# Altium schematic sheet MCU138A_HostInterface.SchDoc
size 431 x 279 mm; Date: Not shown in title block; ApprovedBy: Not shown in title block; CheckedBy: Not shown in title block; Author: Not shown in title block; CompanyName: Not shown in title block; DrawnBy: Jonathan Cohen; Engineer: Not shown in title block; Organization: Not shown in title block; Address1: Not shown in title block; Address2: Not shown in title block; Address3: Not shown in title block; Address4: Not shown in title block; DocumentNumber: 2; Revision: Use project parameter SCH_Rev; SheetNumber: 2; SheetTotal: 3; PageSetup: Record=PageOptions¦CenterHorizontal=True¦CenterVertical=True¦PrintScale=1.00¦XCorrection=1.00¦YCorrection=1.00¦PrintKind=0¦BorderSize=5000000¦LeftOffset=0¦BottomOffset=0¦Orientation=2¦PaperLength=1000¦PaperWidth=1000¦Scale=100¦PaperSource=15¦PrintQuality=600¦MediaType=1¦DitherType=10¦PaperKind=Letter¦PrintScaleMode=1
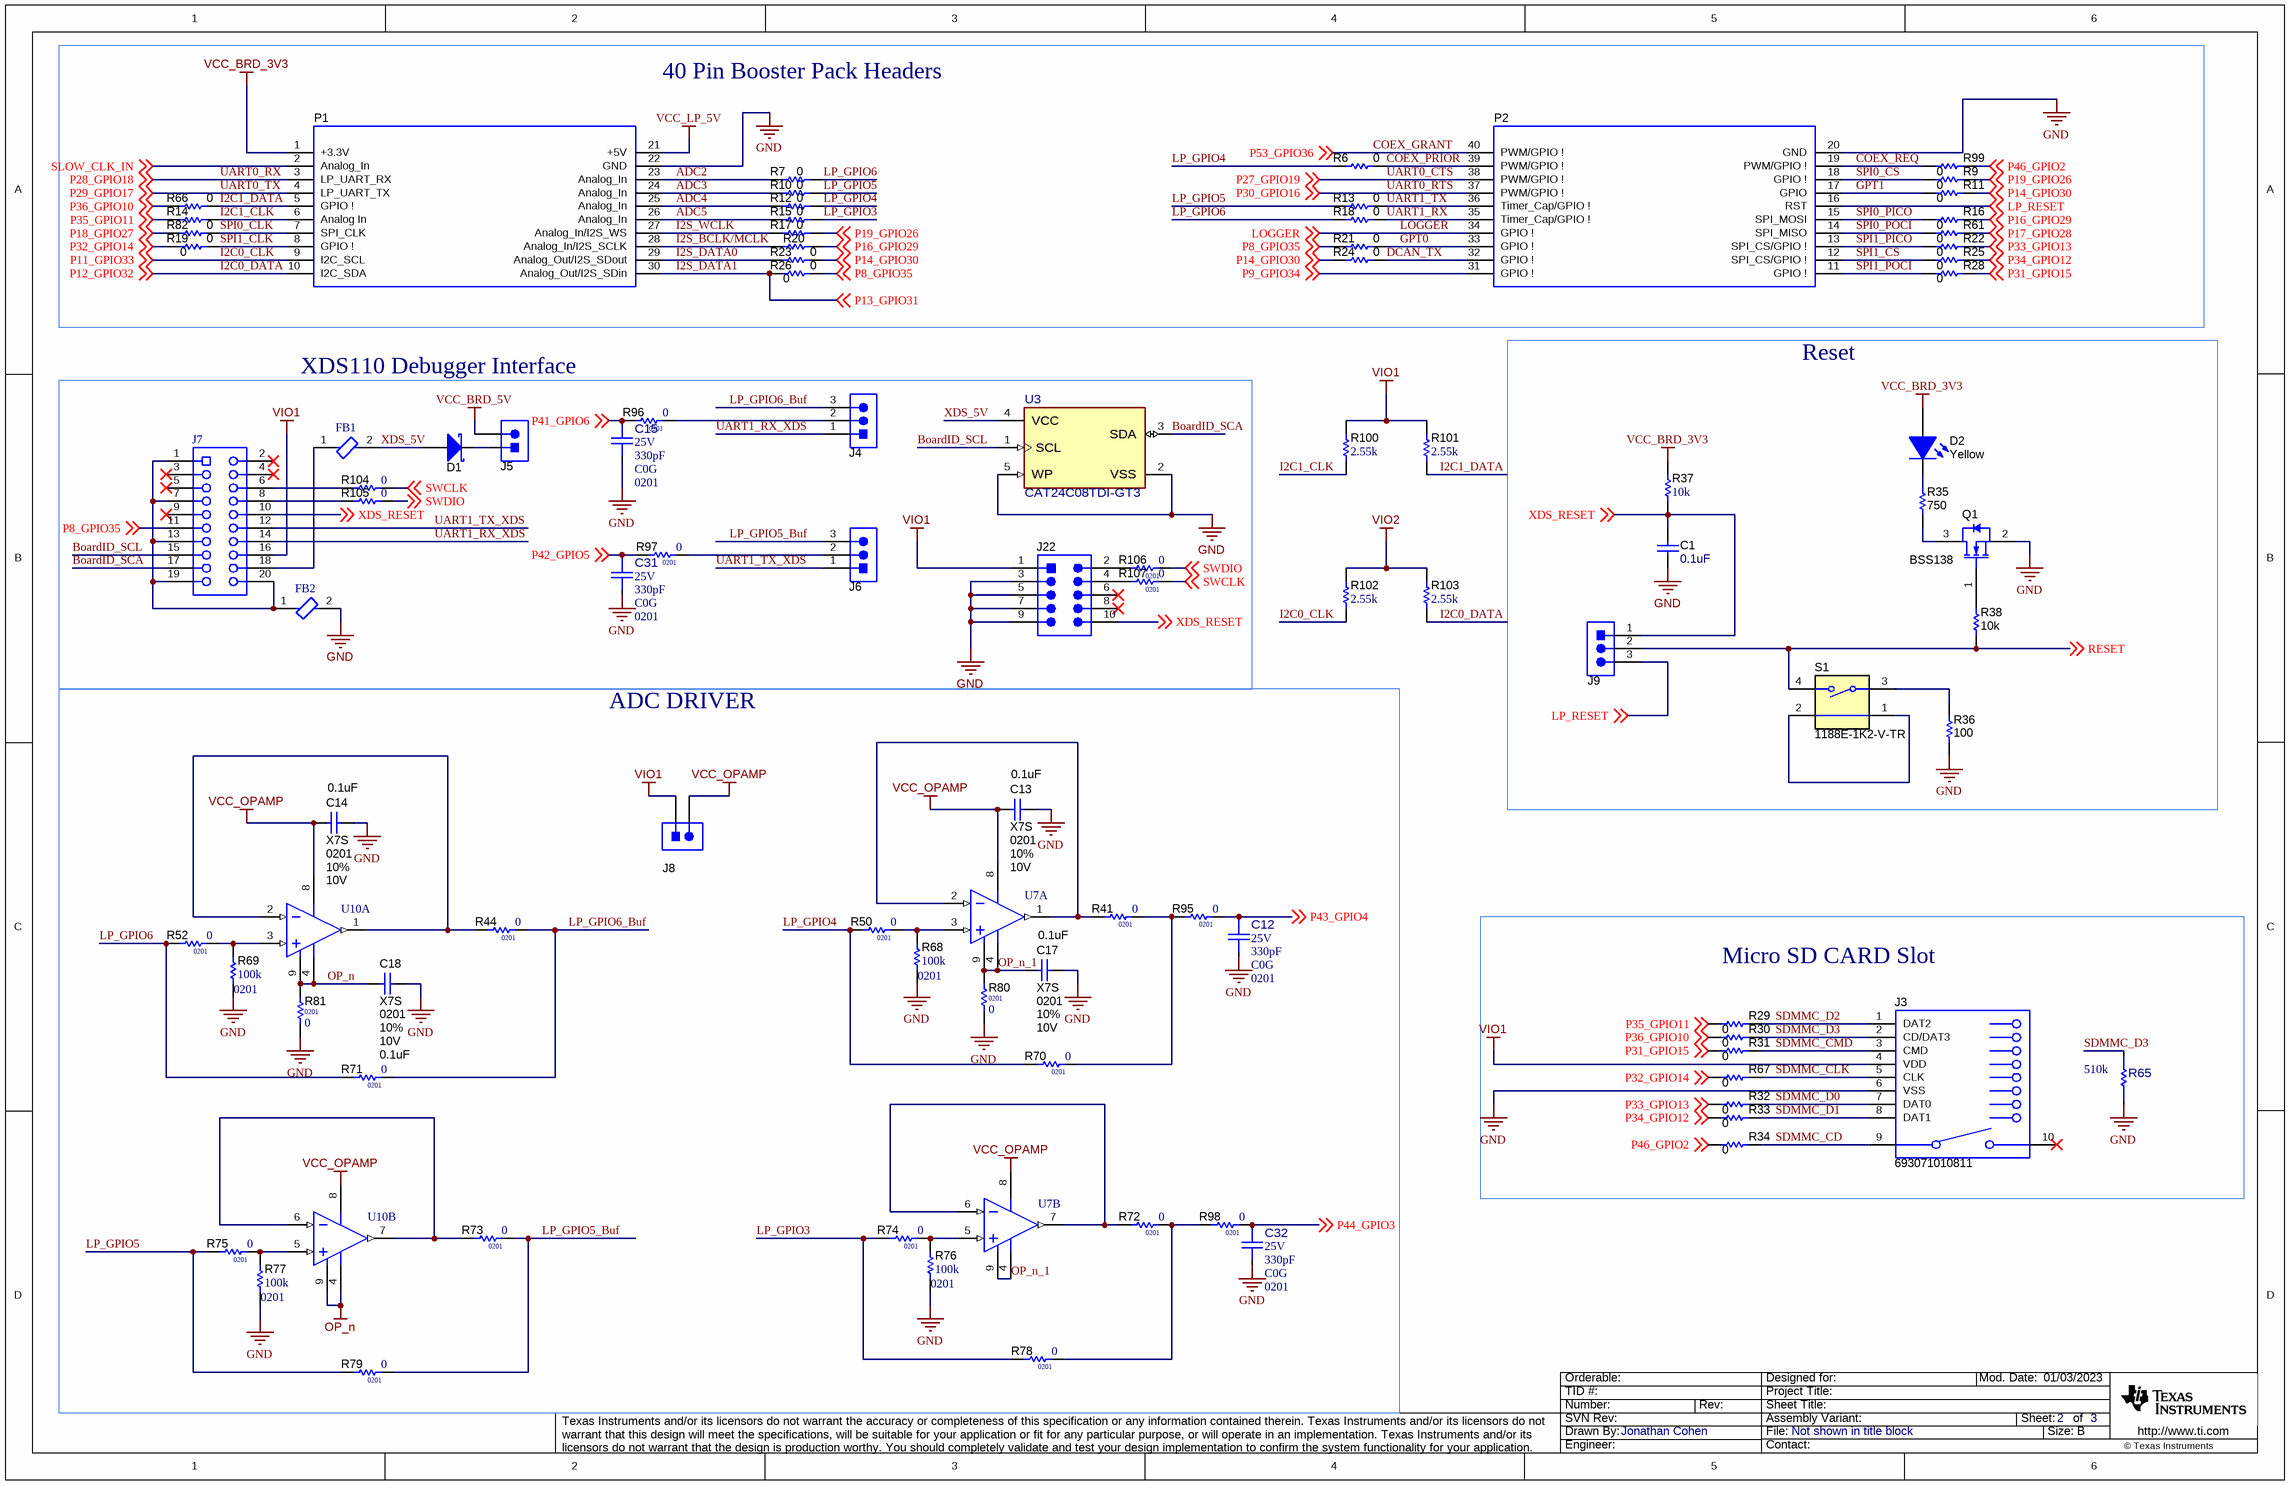
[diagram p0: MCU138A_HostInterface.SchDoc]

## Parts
C1  ValueDisplayed: 0.1uF  [0201]  (hidden comment: GRM033C71A104KE14D)
C12  VDC_V: 25V  ValueDisplayed: 330pF  Temperature Characteristic: C0G  PackageReference: 0201  [FP-GRM0335C1E331FA01D_0201-MFG]  (hidden comment: GRM0335C1E331FA01D)
C13  TempCo: X7S  Tolerance_%: 10%  VDC_V: 10V  ValueDisplayed: 0.1uF  [0201]  (hidden comment: GRM033C71A104KE14D)
C14  TempCo: X7S  Tolerance_%: 10%  VDC_V: 10V  ValueDisplayed: 0.1uF  [0201]  (hidden comment: GRM033C71A104KE14D)
C15  VDC_V: 25V  ValueDisplayed: 330pF  Temperature Characteristic: C0G  PackageReference: 0201  [FP-GRM0335C1E331FA01D_0201-MFG]  (hidden comment: GRM0335C1E331FA01D)
C17  TempCo: X7S  Tolerance_%: 10%  VDC_V: 10V  ValueDisplayed: 0.1uF  [0201]  (hidden comment: GRM033C71A104KE14D)
C18  TempCo: X7S  Tolerance_%: 10%  VDC_V: 10V  ValueDisplayed: 0.1uF  [0201]  (hidden comment: GRM033C71A104KE14D)
C31  VDC_V: 25V  ValueDisplayed: 330pF  Temperature Characteristic: C0G  PackageReference: 0201  [FP-GRM0335C1E331FA01D_0201-MFG]  (hidden comment: GRM0335C1E331FA01D)
C32  VDC_V: 25V  ValueDisplayed: 330pF  Temperature Characteristic: C0G  PackageReference: 0201  [FP-GRM0335C1E331FA01D_0201-MFG]  (hidden comment: GRM0335C1E331FA01D)
D1  MBR130T1G  [SOD-123]  (value not drawn)
D2  value Yellow  [WL-SMCW_YELLOW]  (hidden comment: CMP-0002892-2)
FB1  BLM18PG471SN1D  [FP-BLM18-0_15-t0_8-MFG]  (value not drawn)
FB2  BLM18PG471SN1D  [FP-BLM18-0_15-t0_8-MFG]  (value not drawn)
J3  693071010811  [Molex_693071010811]
J4  CMP-0054796-1  [WURTH_61300311121]  (value not drawn)
J5  61300211121  [WURTH_61300211121]  (value not drawn)
J6  CMP-0054796-1  [WURTH_61300311121]  (value not drawn)
J7  SFH11-PBPC-D10-RA-BK  [Sullins_SFH11-xxxC-D10-RA]  (value not drawn)
J8  61300211121  [WURTH_61300211121]  (value not drawn)
J9  CMP-0054796-1  [WURTH_61300311121]  (value not drawn)
J22  CMP-0075533-1  [Samtec_FTSH-105-01-x-D-K]  (value not drawn)
P1  SSQ-110-03-T-D  [BoosterPack_40pin_J1J3]  (value not drawn)
P2  SSQ-110-03-T-D  [BoosterPack_40pin_J2J4]  (value not drawn)
Q1  PartNumber: BSS138  [SOT-23]  (hidden comment: CMP-0000755-1)
R6  ValueDisplayed: 0  [0402S]  (hidden comment: CMP-0026992-2)
R7  ValueDisplayed: 0  [0402S]  (hidden comment: CMP-0026992-2)
R9  ValueDisplayed: 0  [0402S]  (hidden comment: CMP-0026992-2)
R10  ValueDisplayed: 0  [0402S]  (hidden comment: CMP-0026992-2)
R11  ValueDisplayed: 0  [0402S]  (hidden comment: CMP-0026992-2)
R12  ValueDisplayed: 0  [0402S]  (hidden comment: CMP-0026992-2)
R13  ValueDisplayed: 0  [0402S]  (hidden comment: CMP-0026992-2)
R14  ValueDisplayed: 0  [0402S]  (hidden comment: CMP-0026992-2)
R15  ValueDisplayed: 0  [0402S]  (hidden comment: CMP-0026992-2)
R16  ValueDisplayed: 0  [0402S]  (hidden comment: CMP-0026992-2)
R17  ValueDisplayed: 0  [0402S]  (hidden comment: CMP-0026992-2)
R18  ValueDisplayed: 0  [0402S]  (hidden comment: CMP-0026992-2)
R19  ValueDisplayed: 0  [0402S]  (hidden comment: CMP-0026992-2)
R20  ValueDisplayed: 0  [0402S]  (hidden comment: CMP-0026992-2)
R21  ValueDisplayed: 0  [0402S]  (hidden comment: CMP-0026992-2)
R22  ValueDisplayed: 0  [0402S]  (hidden comment: CMP-0026992-2)
R23  ValueDisplayed: 0  [0402S]  (hidden comment: CMP-0026992-2)
R24  ValueDisplayed: 0  [0402S]  (hidden comment: CMP-0026992-2)
R25  ValueDisplayed: 0  [0402S]  (hidden comment: CMP-0026992-2)
R26  ValueDisplayed: 0  [0402S]  (hidden comment: CMP-0026992-2)
R28  ValueDisplayed: 0  [0402S]  (hidden comment: CMP-0026992-2)
R29  ValueDisplayed: 0  [0402S]  (hidden comment: CMP-0026992-2)
R30  ValueDisplayed: 0  [0402S]  (hidden comment: CMP-0026992-2)
R31  ValueDisplayed: 0  [0402S]  (hidden comment: CMP-0026992-2)
R32  ValueDisplayed: 0  [0402S]  (hidden comment: CMP-0026992-2)
R33  ValueDisplayed: 0  [0402S]  (hidden comment: CMP-0026992-2)
R34  ValueDisplayed: 0  [0402S]  (hidden comment: CMP-0026992-2)
R35  ValueDisplayed: 750  [0603]  (hidden comment: CMP-0025852-4)
R36  ValueDisplayed: 100  [0402]  (hidden comment: CMP-0026656-1)
R37  ValueDisplayed: 10k  [0201]  (hidden comment: RC0201JR-7D10KL)
R38  ValueDisplayed: 10k  [0402]  (hidden comment: CMP-0026825-5)
R41  ValueDisplayed: 0  [0201]  (hidden comment: CRCW02010000Z0ED)
R44  ValueDisplayed: 0  [0201]  (hidden comment: CRCW02010000Z0ED)
R50  ValueDisplayed: 0  [0201]  (hidden comment: CRCW02010000Z0ED)
R52  ValueDisplayed: 0  [0201]  (hidden comment: CRCW02010000Z0ED)
R61  ValueDisplayed: 0  [0402S]  (hidden comment: CMP-0026992-2)
R65  value 510k  [FP-ERJ-2GEJ514X_0402-MFG]  (hidden comment: ERJ-2GEJ514X)
R66  ValueDisplayed: 0  [0402S]  (hidden comment: CMP-0026992-2)
R67  ValueDisplayed: 0  [0402S]  (hidden comment: CMP-0026992-2)
R68  ValueDisplayed: 100k  [0201]  (hidden comment: RC0201DR-07100KL)
R69  ValueDisplayed: 100k  [0201]  (hidden comment: RC0201DR-07100KL)
R70  ValueDisplayed: 0  [0201]  (hidden comment: CRCW02010000Z0ED)
R71  ValueDisplayed: 0  [0201]  (hidden comment: CRCW02010000Z0ED)
R72  ValueDisplayed: 0  [0201]  (hidden comment: CRCW02010000Z0ED)
R73  ValueDisplayed: 0  [0201]  (hidden comment: CRCW02010000Z0ED)
R74  ValueDisplayed: 0  [0201]  (hidden comment: CRCW02010000Z0ED)
R75  ValueDisplayed: 0  [0201]  (hidden comment: CRCW02010000Z0ED)
R76  ValueDisplayed: 100k  [0201]  (hidden comment: RC0201DR-07100KL)
R77  ValueDisplayed: 100k  [0201]  (hidden comment: RC0201DR-07100KL)
R78  ValueDisplayed: 0  [0201]  (hidden comment: CRCW02010000Z0ED)
R79  ValueDisplayed: 0  [0201]  (hidden comment: CRCW02010000Z0ED)
R80  ValueDisplayed: 0  [0201]  (hidden comment: CRCW02010000Z0ED)
R81  ValueDisplayed: 0  [0201]  (hidden comment: CRCW02010000Z0ED)
R82  ValueDisplayed: 0  [0402S]  (hidden comment: CMP-0026992-2)
R95  ValueDisplayed: 0  [0201]  (hidden comment: CRCW02010000Z0ED)
R96  ValueDisplayed: 0  [0201]  (hidden comment: CRCW02010000Z0ED)
R97  ValueDisplayed: 0  [0201]  (hidden comment: CRCW02010000Z0ED)
R98  ValueDisplayed: 0  [0201]  (hidden comment: CRCW02010000Z0ED)
R99  ValueDisplayed: 0  [0402S]  (hidden comment: CMP-0026992-2)
R100  ValueDisplayed: 2.55k  [0201]  (hidden comment: RC0201FR-072K55L)
R101  ValueDisplayed: 2.55k  [0201]  (hidden comment: RC0201FR-072K55L)
R102  ValueDisplayed: 2.55k  [0201]  (hidden comment: RC0201FR-072K55L)
R103  ValueDisplayed: 2.55k  [0201]  (hidden comment: RC0201FR-072K55L)
R104  ValueDisplayed: 0  [0201]  (hidden comment: CRCW02010000Z0ED)
R105  ValueDisplayed: 0  [0201]  (hidden comment: CRCW02010000Z0ED)
R106  ValueDisplayed: 0  [0201]  (hidden comment: CRCW02010000Z0ED)
R107  ValueDisplayed: 0  [0201]  (hidden comment: CRCW02010000Z0ED)
S1  1188E-1K2-V-TR  [SW_1188E]
U3  CAT24C08TDI-GT3  [FP-CAT24C08TDI-GT3_TSOT-23-5-IPC_C]
U7  OPA2211AIDRGR  [DRG0008B]  (value not drawn)  (parts A,B of 2)
U10  OPA2211AIDRGR  [DRG0008B]  (value not drawn)  (parts A,B of 2)

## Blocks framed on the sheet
40 Pin Booster Pack Headers: P1 P2 R6 R7 R9-R26 R28 R61 R66 R82 R99
Reset: C1 D2 J9 Q1 R35-R38 S1
XDS110 Debugger Interface: C15 C31 D1 FB1 FB2 J4-J7 J22 R96 R97 R104-R107 U3
ADC DRIVER: C12-C14 C17 C18 C32 J8 R41 R44 R50 R52 R68-R81 R95 R98 U7 U10
Micro SD CARD Slot: J3 R29-R34 R65 R67

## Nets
GND: C1.2 C12.2 C13.1 C14.1 C15.2 C17.1 C18.2 C31.2 C32.2 FB2.2 J3.6(VSS) J22.3 J22.5 J22.7 J22.9 P1.22(GND) P2.20(GND) Q1.2(S) R36.2 R65.1 R68.1 R69.1 R76.1 R77.1 R80.1 R81.1 U3.2(VSS) U3.5(WP)
OP_n: C18.1 R81.2 U10.4(V-) U10.9(EP)
VCC_BRD_3V3: D2.2(A) P1.1(+3.3V) R37.2
VCC_BRD_5V: J5.2
VCC_LP_5V: P1.21(+5V)
VCC_OPAMP: C13.2 C14.2 J8.2 U7.8(V+) U10.8(V+)
VIO1: J3.4(VDD) J7.16 J8.1 J22.1 R100.2 R101.2
VIO2: R102.2 R103.2
ADC2: P1.23(Analog_In) R7.2
ADC3: P1.24(Analog_In) R10.2
ADC4: P1.25(Analog_In) R12.2
ADC5: P1.26(Analog_In) R15.2
BoardID_SCA: J7.17 U3.3(SDA)
BoardID_SCL: J7.15 U3.1(SCL)
COEX_GRANT: P2.40(PWM/GPIO_!) ; off-sheet P53_GPIO36  [also labelled P53_GPIO36]
COEX_PRIOR: P2.39(PWM/GPIO_!) R6.1
COEX_REQ: P2.19(PWM/GPIO_!) R99.2
DCAN_TX: P2.32(GPIO_!) R24.1
GPT0: P2.33(GPIO_!) R21.1
GPT1: P2.17(GPIO) R11.2
I2C0_CLK: P1.9(I2C_SCL) R102.1 ; off-sheet P11_GPIO33  [also labelled P11_GPIO33]
I2C0_DATA: P1.10(I2C_SDA) R103.1 ; off-sheet P12_GPIO32  [also labelled P12_GPIO32]
I2C1_CLK: P1.6(Analog_In) R14.1 R100.1
I2C1_DATA: P1.5(GPIO_!) R66.1 R101.1
I2S_BCLK/MCLK: P1.28(Analog_In/I2S_SCLK) R20.2
I2S_DATA0: P1.29(Analog_Out/I2S_SDout) R23.2
I2S_DATA1: P1.30(Analog_Out/I2S_SDin) R26.2 ; off-sheet P13_GPIO31  [also labelled P13_GPIO31]
I2S_WCLK: P1.27(Analog_In/I2S_WS) R17.2
LOGGER: P2.34(GPIO_!) ; off-sheet LOGGER
LP_GPIO3: R15.1 R74.1 R78.1
LP_GPIO4: R6.2 R12.1 R50.1 R70.1
LP_GPIO5: R10.1 R13.2 R75.1 R79.1
LP_GPIO5_Buf: J6.3 R73.2 R79.2
LP_GPIO6: R7.1 R18.2 R52.1 R71.1
LP_GPIO6_Buf: J4.3 R44.2 R71.2
LP_RESET: J9.3 P2.16(RST) ; off-sheet LP_RESET
OP_n_1: C17.2 R80.2 U7.4(V-) U7.9(EP)
P8_GPIO35: J7.11 R21.2 R26.1 ; off-sheet P8_GPIO35
P9_GPIO34: P2.31(GPIO_!) ; off-sheet P9_GPIO34
P14_GPIO30: R11.1 R23.1 R24.2 ; off-sheet P14_GPIO30
P16_GPIO29: R16.1 R20.1 ; off-sheet P16_GPIO29
P17_GPIO28: R61.1 ; off-sheet P17_GPIO28
P18_GPIO27: R82.2 ; off-sheet P18_GPIO27
P19_GPIO26: R9.1 R17.1 ; off-sheet P19_GPIO26
P31_GPIO15: R28.1 R31.2 ; off-sheet P31_GPIO15
P32_GPIO14: R19.2 R67.2 ; off-sheet P32_GPIO14
P33_GPIO13: R22.1 R32.2 ; off-sheet P33_GPIO13
P34_GPIO12: R25.1 R33.2 ; off-sheet P34_GPIO12
P35_GPIO11: R14.2 R29.2 ; off-sheet P35_GPIO11
P36_GPIO10: R30.2 R66.2 ; off-sheet P36_GPIO10
P41_GPIO6: C15.1 R96.1 ; off-sheet P41_GPIO6
P42_GPIO5: C31.1 R97.1 ; off-sheet P42_GPIO5
P43_GPIO4: C12.1 R95.2 ; off-sheet P43_GPIO4
P44_GPIO3: C32.1 R98.2 ; off-sheet P44_GPIO3
P46_GPIO2: R34.2 R99.1 ; off-sheet P46_GPIO2
RESET: J9.2 R38.1 S1.4 ; off-sheet RESET
SDMMC_CD: J3.9 R34.1
SDMMC_CLK: J3.5(CLK) R67.1
SDMMC_CMD: J3.3(CMD) R31.1
SDMMC_D0: J3.7(DAT0) R32.1
SDMMC_D1: J3.8(DAT1) R33.1
SDMMC_D2: J3.1(DAT2) R29.1
SDMMC_D3: J3.2(CD/DAT3) R30.1 R65.2
SLOW_CLK_IN: P1.2(Analog_In) ; off-sheet SLOW_CLK_IN
SPI0_CLK: P1.7(SPI_CLK) R82.1
SPI0_CS: P2.18(GPIO_!) R9.2
SPI0_PICO: P2.15(SPI_MOSI) R16.2
SPI0_POCI: P2.14(SPI_MISO) R61.2
SPI1_CLK: P1.8(GPIO_!) R19.1
SPI1_CS: P2.12(SPI_CS/GPIO_!) R25.2
SPI1_PICO: P2.13(SPI_CS/GPIO_!) R22.2
SPI1_POCI: P2.11(GPIO_!) R28.2
SWCLK: R104.2 R107.2 ; off-sheet SWCLK
SWDIO: R105.2 R106.2 ; off-sheet SWDIO
UART0_CTS: P2.38(PWM/GPIO_!) ; off-sheet P27_GPIO19  [also labelled P27_GPIO19]
UART0_RTS: P2.37(PWM/GPIO_!) ; off-sheet P30_GPIO16  [also labelled P30_GPIO16]
UART0_RX: P1.3(LP_UART_RX) ; off-sheet P28_GPIO18  [also labelled P28_GPIO18]
UART0_TX: P1.4(LP_UART_TX) ; off-sheet P29_GPIO17  [also labelled P29_GPIO17]
UART1_RX: P2.35(Timer_Cap/GPIO_!) R18.1
UART1_RX_XDS: J4.1 J7.14
UART1_TX: P2.36(Timer_Cap/GPIO_!) R13.1
UART1_TX_XDS: J6.1 J7.12
XDS_5V: D1.2(A) FB1.2 U3.4(VCC)
XDS_RESET: C1.1 J7.10 J9.1 J22.10 R37.1 ; off-sheet XDS_RESET
NetD1_1: D1.1(K) J5.1
NetD2_1: D2.1(K) R35.1
NetFB1_1: FB1.1 J7.18
NetFB2_1: FB2.1 J7.1 J7.7 J7.13 J7.19 J7.20
NetJ4_2: J4.2 R96.2
NetJ6_2: J6.2 R97.2
NetJ7_6: J7.6 R104.1
NetJ7_8: J7.8 R105.1
NetJ22_2: J22.2 R106.1
NetJ22_4: J22.4 R107.1
NetQ1_1: Q1.1(G) R38.2
NetQ1_3: Q1.3(D) R35.2
NetR36_1: R36.1 S1.3
NetR41_1: R41.1 U7.1(OUT_A) U7.2(IN_A-)
NetR41_2: R41.2 R70.2 R95.1
NetR44_1: R44.1 U10.1(OUT_A) U10.2(IN_A-)
NetR50_2: R50.2 R68.2 U7.3(IN_A+)
NetR52_2: R52.2 R69.2 U10.3(IN_A+)
NetR72_1: R72.1 U7.6(IN_B-) U7.7(OUT_B)
NetR72_2: R72.2 R78.2 R98.1
NetR73_1: R73.1 U10.6(IN_B-) U10.7(OUT_B)
NetR74_2: R74.2 R76.2 U7.5(IN_B+)
NetR75_2: R75.2 R77.2 U10.5(IN_B+)
NetS1_1: S1.1 S1.2

Not connected (* = marked no-connect by the designer): J3 10*; J7 2* 3* 4* 5* 9*; J22 6* 8*

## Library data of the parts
C1 = CMP-0064969-1: CAP, CERM, 0.1 uF, 10 V,+/- 10%, X7S, 0201; Manufacturer: MuRata; TaMin_C: -55°C; Polarized: N; SizeAreaWB_mm2: 2.08; Value1: Unknown; U/M: EA; Value: 0.1uF; TaMax_C: 125°C; SizeZ_mm: 0.26; SizeX_mm: 0.6; SizeY_mm: 0.3; Value2: 10V; SizeArea_mm2: 0.18; Cap_F: 100nF; AEC Category: Q200
C12 C15 C31 C32 = CMP-0098216-1: Chip Multilayer Ceramic Capacitors for General Purpose, 0201, 330pF, C0G, 30ppm/°C, 1%, 25V; Manufacturer: Murata; SizeZ_mm: 0.33mm; AEC Qualified: No
C13 C14 C17 C18 = CMP-0064969-1: CAP, CERM, 0.1 uF, 10 V,+/- 10%, X7S, 0201; Manufacturer: MuRata; TaMin_C: -55°C; Polarized: N; SizeAreaWB_mm2: 2.08; Value1: Unknown; U/M: EA; Value: 0.1uF; TaMax_C: 125°C; SizeZ_mm: 0.26; SizeX_mm: 0.6; SizeY_mm: 0.3; SizeArea_mm2: 0.18; Cap_F: 100nF; AEC Category: Q200
D1 = CMP-0028547-1: Diode, Schottky, 30 V, 1 A, SOD-123; Manufacturer: ON Semiconductor; Io_A: 1A; Green_Lifecycle: Active; SizeAreaWB_mm2: 13.095; Vr_V: 30V; Green_REACh: Passed; TJmax_C: 125°C; U/M: EA; Value: 30V; SizeZ_mm: 1.35; SizeX_mm: 3.85; SizeY_mm: 1.7; Vf_V: 4.7dV; Value2: 0.47V; SizeArea_mm2: 6.545; AEC Category: Q101; RJC_CperW: 108
D2 = CMP-0002892-2: LED, Yellow, SMD; Manufacturer: Wurth Elektronik; PartNumber: 150060YS75000; Alternate Manufacturer: Everlight; Alternate PartNumber: 19-217/Y5C-AM1N1VY/3T; Type: AlInGaP; Vf_V: 2V; Io_A: 20mA; Value1: W; U/M: EA
FB1 FB2 = CMP-0686-00587-3: Chip Ferrite Bead, 0603, 470Ω @ 100MHz, 0.2Ω, 25%, 1A; DC Resistance (DCR): 200mR; Number of Circuits: 1; Material: Steel; Impedance: 470R
J3 = CMP-0078832-1: MicroSD Card Connector, R/A, Gold, SMT; Manufacturer: Wurth Elektronik; Pitch_mm: 1.1; Gender: Female; Cert_UL: Y; Voltage_V: 100V; Current_A: 5dA; Row_Count: 1
J4 J6 J9 = CMP-0054796-1: Header, 2.54 mm, 3x1, Gold, TH; PartNumber: 61300311121; Manufacturer: Wurth Elektronik; Alternate Manufacturer: ----; CNHeader: TRUE; Green_Lifecycle: Active; Green_REACh: Passed; CT: FALSE
J5 J8 = CMP-0054794-1: Header, 2.54 mm, 2x1, Gold, TH; Manufacturer: Wurth Elektronik; CNHeader: TRUE; Green_Lifecycle: Active; Green_REACh: Passed; CT: FALSE
J7 = CMP-0074634-1: Receptacle, 2.54mm, 10x2, Gold, R/A, TH; Manufacturer: Sullins Connector Solutions; CNHeader: False; Current_A: 3A; Gender: Female; Voltage_V: 1kV; CompType: Socket Strip; Row_Count: 2; Pitch_mm: 2.54; CT: True; Cert_UL: Y
J22 = CMP-0075533-1: Header, 1.27 mm, 5x2, Gold, TH; PartNumber: FTSH-105-01-F-D-K; Manufacturer: Samtec; Alternate Manufacturer: ----; Pitch_mm: 1.27; Gender: Male; Green_REACh: Passed; CT: False; Shrouded: Y; Green_Lifecycle: Active; Row_Count: 2
P1 = CMP-0003837-2: Receptacle, 2.54mm, 10x2, Tin, TH; Alternate PartNumber: CRD-081413-A-G; Manufacturer: Samtec; Alternate Manufacturer: Major League Electronics; Note: Booster Pack 40 pin J1 and J3; Green_Lifecycle: Active; Green_REACh: Incomplete
P2 = CMP-0078266-2: Receptacle, 2.54mm, 10x2, Tin, TH; Alternate PartNumber: CRD-081413-A-G; Manufacturer: Samtec; Alternate Manufacturer: Major League Electronics; Note: Booster Pack 40 pin J2 and J4; Green_REACh: Incomplete; Green_Lifecycle: Active
Q1 = CMP-0000755-1: MOSFET, N-CH, 50 V, 0.22 A, SOT-23; Manufacturer: Fairchild Semiconductor; Alternate Manufacturer: ON; Alternate PartNumber: BSS138LT1G; U/M: EA; ChType: N; Value: 50V; Rdson45_ohm: 6; Value2: 1.7 nC; QgTyp_nC: 1.7; Vgs_V: 20V; IdsMax_A: 2.2dA; SizeZ_mm: 1.1; SizeX_mm: 2.5; SizeY_mm: 3; SizeArea_mm2: 7.5; AEC Category: Q101; SizeAreaWB_mm2: 14
R6 R7 R9-R26 R28-R34 R61 R66 R67 R82 R99 = CMP-0026992-2: RES, 0, 5%, 0.063 W, 0402; PartNumber: ERJ-2GE0R00X; Manufacturer: Panasonic; Alternate Manufacturer: YAGEO; Alternate PartNumber: RC0402JR-070RL; CompType: Resistor; Value: 0; Value_Code: 0000; Power_W: 63mW; Value2: 0.063W; VDC_V: 50V; TempCo: 600 ppm/C; SizeArea_mm2: 0.5; SizeX_mm: 1; SizeZ_mm: 0.6; EIA_Code: E24; U/M: EA; AEC Category: Q200
R35 = CMP-0025852-4: RES, 750, 5%, 0.1 W, AEC-Q200 Grade 0, 0603; PartNumber: CRCW0603750RJNEA; Manufacturer: Vishay-Dale; Alternate Manufacturer: YAGEO; Alternate PartNumber: RC0603JR-07750RL; Value: 750; Value_Code: 750R; Power_W: 100mW; Value2: 0.1W; VDC_V: 75V; TempCo: 200 ppm/C; EIA_Code: E24; SizeArea_mm2: 1.28; SizeX_mm: 1.6; SizeY_mm: 0.8; SizeZ_mm: 1; AEC Category: Q200; AEC Qualified: Y; AEC Grade: 0
R36 = CMP-0026656-1: RES, 100, 1%, 0.1 W, 0402; PartNumber: ERJ-2RKF1000X; Manufacturer: Panasonic; Alternate Manufacturer: ----; CompType: Resistor; Value: 100; Value_Code: 100R; Power_W: 100mW; Value2: 0.1W; VDC_V: 50V; TempCo: 100 ppm/C; EIA_Code: E96; U/M: EA; SizeX_mm: 1; SizeY_mm: 0.5; SizeZ_mm: 0.6; AEC Category: Q200
R37 = CMP-0027186-1: RES, 10 k, 5%, 0.05 W, 0201; Manufacturer: Yageo America; Power_W: 50mW; TempCo: 200 ppm/C; Value_Code: 10k0; U/M: EA; Value: 10k; EIA_Code: E24; SizeX_mm: 0.6; SizeY_mm: 0.3; SizeZ_mm: 0.26; Value2: 0.05W; SizeArea_mm2: 0.18; AEC Qualified: N; VDC_V: 25V; AEC Category: Q200
R38 = CMP-0026825-5: RES, 10 k, 5%, 0.063 W, AEC-Q200 Grade 0, 0402; PartNumber: CRCW040210K0JNED; Manufacturer: Vishay-Dale; Alternate Manufacturer: YAGEO; Alternate PartNumber: RC0402JR-0710KL; Value: 10k; Value_Code: 10k0; Power_W: 63mW; Value2: 0.063W; VDC_V: 50V; TempCo: 200 ppm/C; EIA_Code: E24; SizeX_mm: 1; SizeY_mm: 0.5; SizeZ_mm: 0.6; AEC Qualified: Y; AEC Category: Q200; AEC Grade: 0
R41 R44 R50 R52 R70-R75 R78-R81 R95-R98 R104-R107 = CMP-0027008-4: RES, 0, 5%, 0.05 W, 0201; Manufacturer: Vishay-Dale; Power_W: 50mW; TempCo: ppm/C; Value_Code: 0000; Value: 0; EIA_Code: E24; SizeX_mm: 0.6; SizeY_mm: 0.3; SizeZ_mm: 0.26; Value2: 0.05W; SizeArea_mm2: 0.18; AEC Qualified: N; AEC Category: Q200
R65 = CMP-0095637-1: 510 kOhms ±5% 0.1W, 1/10W Chip Resistor 0402 (1005 Metric) Automotive AEC-Q200 Thick Film; Manufacturer: Panasonic; VDC_V: 50V; SizeZ_mm: 0.4mm; Power_W: 100mW; AEC Qualified: Yes; TempCo: 200ppm/°C; AEC Grade: Grade 0
R68 R69 R76 R77 = CMP-0028132-1: RES, 100 k, 0.5%, 0.05 W, 0201; Manufacturer: Yageo America; Power_W: 50mW; TempCo: 200 ppm/C; U/M: EA; Value: 100k; EIA_Code: E192; SizeX_mm: 0.6; SizeY_mm: 0.3; SizeZ_mm: 0.26; Value2: 0.05W; SizeArea_mm2: 0.18; AEC Qualified: N; VDC_V: 25V; AEC Category: Q200
R100-R103 = CMP-0027564-1: RES, 2.55 k, 1%, 0.05 W, 0201; Manufacturer: Yageo America; Power_W: 50mW; TempCo: 200 ppm/C; Value_Code: 2k55; U/M: EA; Value: 2.55k; EIA_Code: E96; SizeX_mm: 0.6; SizeY_mm: 0.3; SizeZ_mm: 0.26; Value2: 0.05W; SizeArea_mm2: 0.18; AEC Qualified: N; VDC_V: 25V; AEC Category: Q200
S1 = CMP-0002328-1: Switch, SPST, 0.05 A, 12 VDC, SMD; Manufacturer: Diptronics; CurrentRating_mA: 50A; PositionCount: 1; SizeX_mm: 7.8; SizeY_mm: 3.5; SizeArea_mm2: 27.3; VDC_V: 12V; SizeAreaWB_mm2: 53.9
U3 = CMP-0087170-1: 8KB I2C SER EEPROM TSOT 23; Manufacturer: ON Semiconductor; SizeZ_mm: 1mm
U7 U10 = CMP-0040617-1: 1.1 nV/rtHz Noise, Low Power, Precision Operational Amplifier, 4.5 to 36 V, -40 to 125 degC, 8-pin SON (DRG8), Green (RoHS & no Sb/Br); Manufacturer: Texas Instruments; IIB(Max)(pA): 175000; Slew Rate(Typ)(V/us): 27; GBW(Typ)(MHz): 45; Total Supply Voltage(Max)(+5V is 5, +/-5V is 10): 36; Packing: LARGE T&R; Offset Drift(Typ)(uV/C): 0.35; CMRR(Min)(dB): 114; Iq per channel(Max)(mA): 4.5; Rating: Catalog; Sub Family: High Supply Voltage Amplifier (>=30V), Low Noise Amp (<=10nV/rtHz), Low Offset Voltage Amplifier (<=500uV), Precision Amplifier; Number of Channels: 2; Vio (25C)(Max)(mV): 0.15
